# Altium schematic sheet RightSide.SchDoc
size A4; SheetNumber: 2; SheetTotal: 3
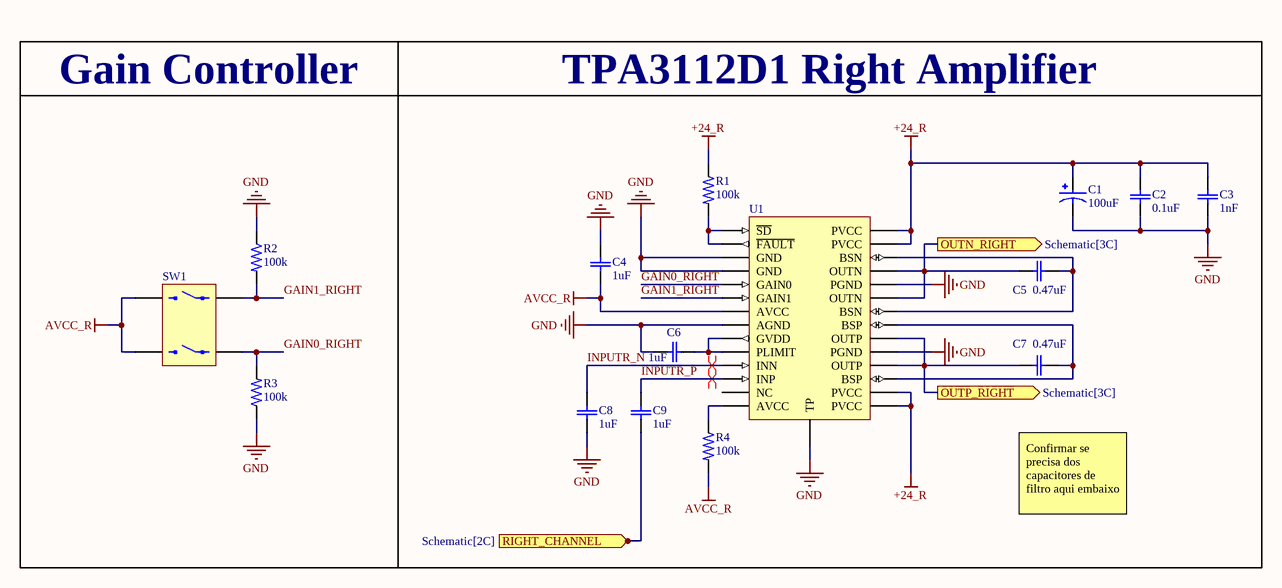
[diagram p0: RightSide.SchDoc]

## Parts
C1  100uF  [CAPRADIAL_16X10]
C2  0.1uF  [CERAMIC0805]
C3  1nF  [CERAMIC0603]
C4  1uF  [CERAMIC0603]
C5  0.47uF  [CERAMIC0603]
C6  1uF  [CERAMIC0603]
C7  0.47uF  [CERAMIC0603]
C8  1uF  [CERAMIC0603]
C9  1uF  [CERAMIC0603]
R1  100k  [RES0603]
R2  100k  [RES0603]
R3  100k  [RES0603]
R4  100k  [RES0603]
SW1  DIP SWITCH - 2 POS  [KF1001 - 2 POS]  (value not drawn)
U1  TPA3112D1  [HTSSOP-28]  (value not drawn)

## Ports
OUTN_RIGHT (out, see Schematic[3C]), OUTP_RIGHT (out, see Schematic[3C]), RIGHT_CHANNEL (in, see Schematic[2C])

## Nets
+24_R: C1.P C2.2(C2) C3.2(C2) R1.1 U1.15(PVCC) U1.16(PVCC) U1.27(PVCC) U1.28(PVCC)
AVCC_R: C4.2(C2) R4.2 SW1.2 SW1.3 U1.7(AVCC)
GND: C1.N C2.1(C1) C3.1(C1) C4.1(C1) C6.2(C2) C8.1(C1) R2.1 R3.1 U1.3(GND) U1.4(GND) U1.8(AGND) U1.19(PGND) U1.24(PGND) U1.29(TP)
GAIN0_RIGHT: R3.2 SW1.1 U1.5(GAIN0)
GAIN1_RIGHT: R2.2 SW1.4 U1.6(GAIN1)
INPUTR_N: C8.2(C2) U1.11(INN)
INPUTR_P: C9.2(C2) U1.12(INP)
OUTN_RIGHT: C5.2(C2) U1.23(OUTN) U1.25(OUTN) ; port OUTN_RIGHT
OUTP_RIGHT: C7.2(C2) U1.18(OUTP) U1.20(OUTP) ; port OUTP_RIGHT
RIGHT_CHANNEL: C9.1(C1) ; port RIGHT_CHANNEL
NetC5_1: C5.1(C1) U1.22(BSN) U1.26(BSN)
NetC6_1: C6.1(C1) U1.9(GVDD) U1.10(PLIMIT)
NetC7_1: C7.1(C1) U1.17(BSP) U1.21(BSP)
NetR1_2: R1.2 U1.1(~{SD}) U1.2(~{FAULT})
NetR4_1: R4.1 U1.14(AVCC)

Not connected (* = marked no-connect by the designer): U1 13(NC)

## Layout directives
differential pair: INPUTR_N, INPUTR_P

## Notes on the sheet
- Gain Controller
- TPA3112D1 Right Amplifier
- Confirmar se precisa dos capacitores de filtro aqui embaixo

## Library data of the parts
C1 = CAP ELETRO/TANT: MP: EEU-EE2W560; MF: Panasonic
C2-C9 = Cap: MF: KEMET; MP: TAJC226M025RNJ
R1-R4 = RESISTOR SMD: MP: 3-1879460-6
U1 = TPA3112D1: 25W Filter-Free Mono Class-D Audio Power Amplifier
